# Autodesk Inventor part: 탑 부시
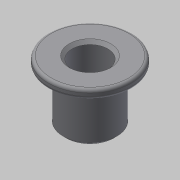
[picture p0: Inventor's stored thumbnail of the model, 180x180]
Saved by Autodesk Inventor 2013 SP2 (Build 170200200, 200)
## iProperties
Created: 2016-08
Part Number: 탑 부시
Material: 스테인리스강
Document SubType Name: Modeling
Designer: mduedu
Density: 8.08 g/cm^3
Author: mduedu
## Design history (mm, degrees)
sketch "스케치1"
  geometry: L1 (0, 0)-(9, 0); L2 (9, 0)-(9, 17); L3 (0, 20)-(0, 0); L4 (9, 17)-(14, 17); L5 (14, 17)-(14, 20); L6 (14, 20)-(0, 20)
  constraints: 12 end point, 2 horizontal, 2 parallel, 2 perpendicular
  dimensions: "d0" = 9 distance between parallel lines of L2 L3; "d2" = 20 distance of L3.start L1.start; "d3" = 14 distance between parallel lines of L5 L3; "d4" = 3 distance of L4.end L5.end
revolve "회전1" sketch "스케치1" stored, may be unused: angle "d5" = 90 deg
hole "구멍1" diameter "d8" = 12; stored, may be unused: countersink angle "d12" = 90 deg, drill point angle "d14" = 118 deg; dims "d6" = 10, "d7" = 10, "d9" = 6, "d10" = 4, "d11" = 2, "d13" = 8
chamfer "모따기1" distance "d15" = 1; stored, may be unused: second distance "d16" = 2, angle "d17" = 45 deg
fillet "모깎기1" dims "d18" = 1
node "솔리드1"
